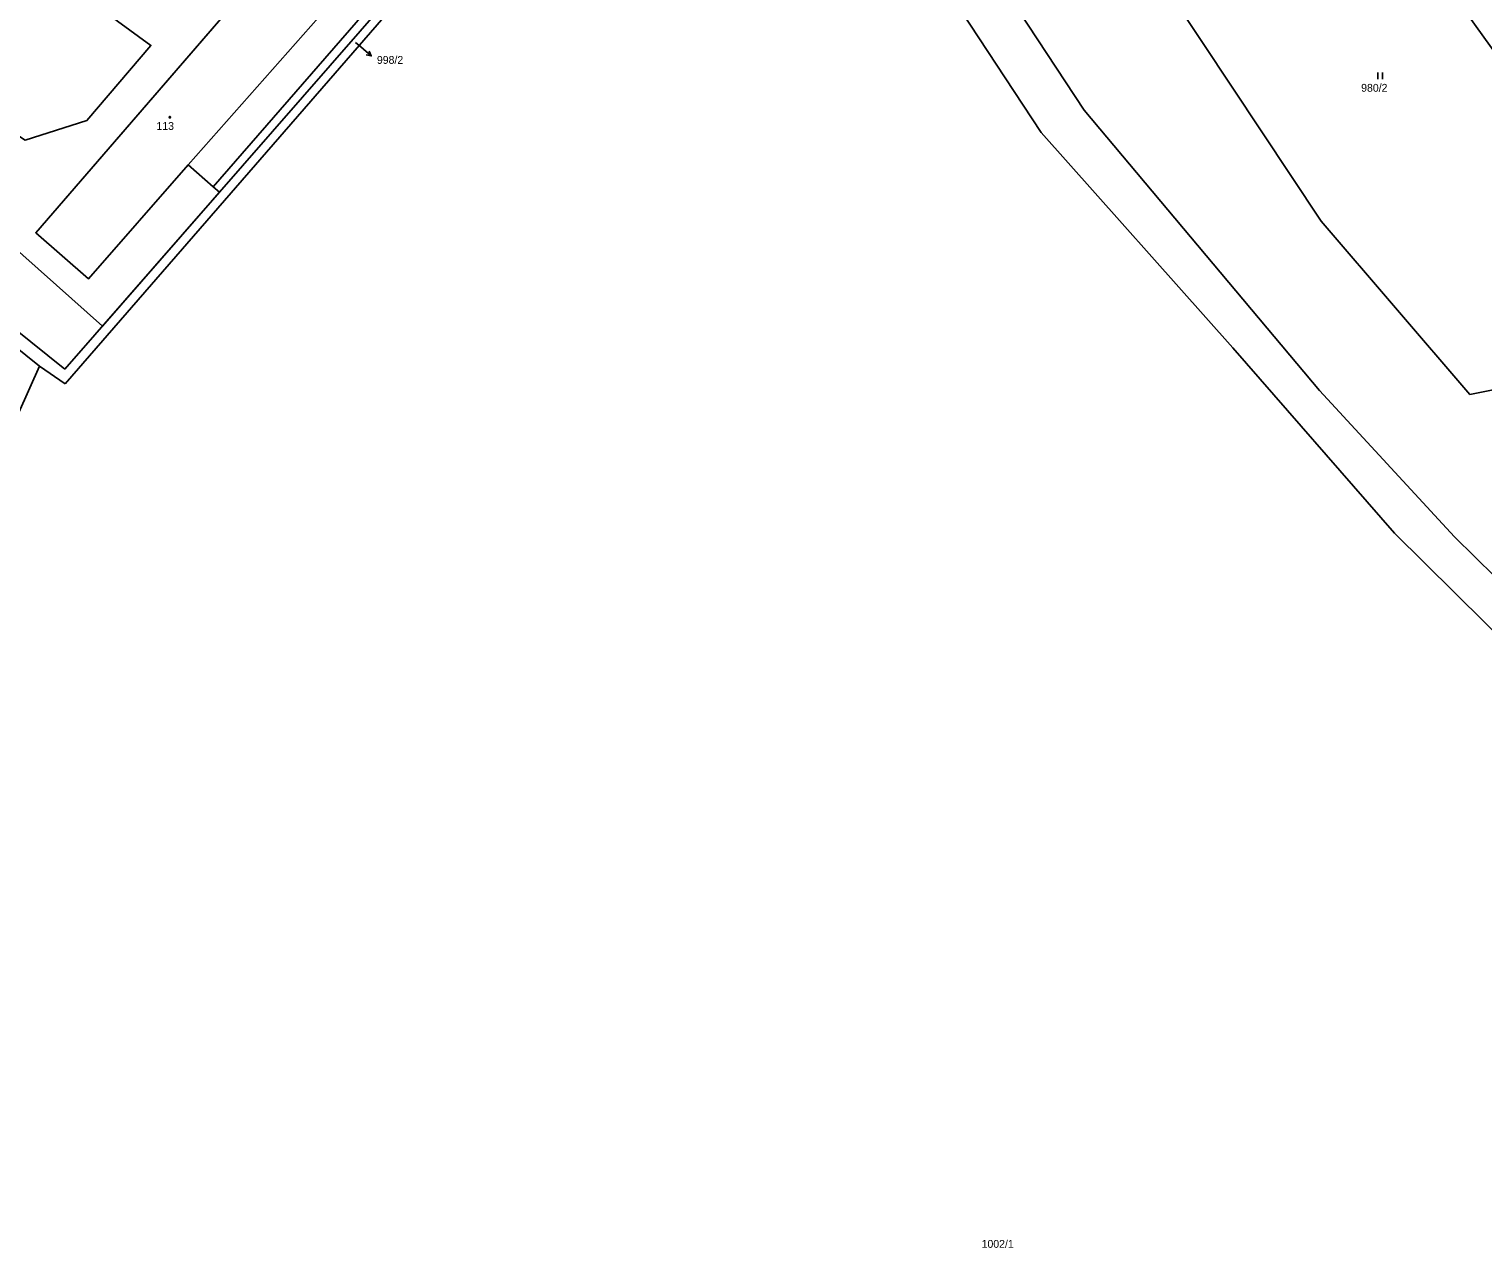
# Model space of a CAD drawing. Extents: x -850689 to -847910, y -1058374 to -1054747.
# Drawn here: x -849297.1 to -848982.2, y -1056708 to -1056444.2 of the extents above; entities that cross this region are included whole.
import ezdxf

# ---------------------------------------------------------------- set-up
doc = ezdxf.new("R2010")
doc.units = 0
for name, color, linetype in [('KN_BREMENA', 7, 'Continuous'), ('KN_HRANICE', 7, 'Continuous'), ('KN_KULTURY', 7, 'Continuous'), ('KN_PARCELY', 7, 'Continuous'), ('KN_SLUCKY', 7, 'Continuous'), ('KN_STAVEBNI', 7, 'Continuous')]:
    doc.layers.add(name, color=color, linetype=linetype)

# ---------------------------------------------------------------- blocks, each defined once
blk = doc.blocks.new('306')
for p, q in [((-0.5, 1.5), (-0.5, 0)), ((0.5, 0), (0.5, 1.5))]:
    blk.add_line(p, q)
blk = doc.blocks.new('10292')
blk.add_line((0, 3), (0, 0))
blk.add_lwpolyline([(-0.5, 2), (0, 3), (0.5, 2)])
blk = doc.blocks.new('402')
blk.add_lwpolyline([(0.09, 0.15), (0.18, 0), (0.09, -0.15), (-0.09, -0.15), (-0.18, 0), (-0.09, 0.15), (0.09, 0.15)])

msp = doc.modelspace()

# ---------------------------------------------------------------- linework, layer by layer
at = {"layer": 'KN_BREMENA'}
for points in [[(-849355.23, -1056367.43), (-849351.69, -1056370.82), (-849349.93, -1056375.07), (-849350.77, -1056418.49), (-849350.24, -1056427.3), (-849345.77, -1056436.61), (-849342.23, -1056439.43), (-849327.01, -1056449.14), (-849298.02, -1056468.19), (-849284.6, -1056463.96), (-849270.77, -1056447.7), (-849287.91, -1056435.18), (-849282.02, -1056427.2), (-849264.01, -1056440.34), (-849244.44, -1056411.59), (-849258.75, -1056401.09), (-849252.32, -1056392.28), (-849210.21, -1056427.21)], [(-849228.87, -1056429.39), (-849225.51, -1056425.01), (-849233.09, -1056418.39), (-849236.55, -1056422.35), (-849241.09, -1056418.38), (-849249.75, -1056428.29), (-849246.39, -1056431.22), (-849295.7, -1056488.26), (-849284.26, -1056498.23), (-849262.65, -1056473.57), (-849257.24, -1056478.3), (-849255.9, -1056479.47)], [(-849255.9, -1056479.47), (-849281.24, -1056508.47), (-849305.2, -1056487.17)]]:
    msp.add_lwpolyline(points, dxfattribs=at)
at = {"layer": 'KN_HRANICE'}
for p, q in [((-849001.93, -1056418.36), (-848977.76, -1056451.81)), ((-849210.21, -1056427.21), (-849289.39, -1056517.79)), ((-849289.35, -1056520.97), (-849207.62, -1056426.96)), ((-849104.83, -1056425.71), (-849077.96, -1056466.55)), ((-849295.7, -1056488.26), (-849246.39, -1056431.22)), ((-849017.3, -1056485.72), (-849052.06, -1056433.36)), ((-849257.24, -1056478.3), (-849221.16, -1056436.85)), ((-849068.63, -1056461.72), (-849085.71, -1056435.76)), ((-849289.39, -1056517.79), (-849366.02, -1056456.29)), ((-849366.76, -1056459.53), (-849294.89, -1056517.18)), ((-849017.61, -1056522.4), (-849068.63, -1056461.72)), ((-849077.96, -1056466.55), (-849036.41, -1056513.21)), ((-849284.26, -1056498.23), (-849262.65, -1056473.57)), ((-849262.65, -1056473.57), (-849257.24, -1056478.3)), ((-848985.11, -1056523.29), (-849017.3, -1056485.72)), ((-849295.7, -1056488.26), (-849284.26, -1056498.23)), ((-849036.41, -1056513.21), (-849001.42, -1056553.28)), ((-849294.89, -1056517.18), (-849366.33, -1056676.64)), ((-849294.89, -1056517.18), (-849289.35, -1056520.97)), ((-848988.42, -1056554.12), (-849017.61, -1056522.4)), ((-848979.67, -1056522.23), (-848985.11, -1056523.29)), ((-849001.42, -1056553.28), (-848879.42, -1056673.93)), ((-848873.55, -1056667.07), (-848988.42, -1056554.12))]:
    msp.add_line(p, q, dxfattribs=at)
at = {"layer": 'KN_PARCELY'}
msp.add_line((-849226.43, -1056447.1), (-849225.32, -1056448.05), dxfattribs=at)
at = {"layer": 'KN_SLUCKY'}
msp.add_line((-849262.65, -1056473.57), (-849234.42, -1056441.65), dxfattribs=at)
at = {"layer": 'KN_STAVEBNI'}
for p, q in [((-849295.7, -1056488.26), (-849246.39, -1056431.22)), ((-849262.65, -1056473.57), (-849234.42, -1056441.65)), ((-849284.26, -1056498.23), (-849262.65, -1056473.57)), ((-849295.7, -1056488.26), (-849284.26, -1056498.23))]:
    msp.add_line(p, q, dxfattribs=at)

# ---------------------------------------------------------------- block references
at = {"layer": 'KN_KULTURY'}
for name, p in [('306', (-849004.48, -1056455.04)), ('402', (-849266.66, -1056463.26))]:
    msp.add_blockref(name, p, dxfattribs=at)
at = {"layer": 'KN_PARCELY', "rotation": -130.53040299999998}
msp.add_blockref('10292', (-849225.32, -1056448.05), dxfattribs=at)

# ---------------------------------------------------------------- texts
at = {"layer": 'KN_PARCELY'}
for s, height, p in [('998/2', 0.1, (-849226.67, -1056447.1)), ('998/2', 1.7, (-849221.8, -1056451.7)), ('980/2', 1.7, (-849008.61, -1056457.74)), ('113', 1.7, (-849269.55, -1056466)), ('1002/1', 1.7, (-849090.82, -1056708))]:
    msp.add_text(s, height=height, dxfattribs=at).set_placement(p)

doc.saveas('drawing.dxf')
